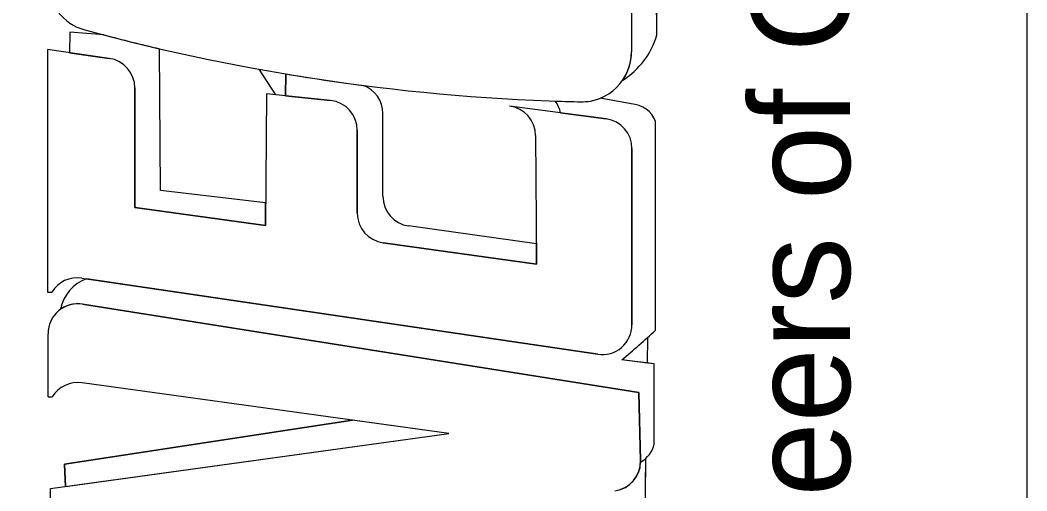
# Model space of a CAD drawing. Extents: x 1485751 to 1485785, y 230696.6 to 230718.6.
# Drawn here: x 1485783.769 to 1485784.533, y 230715.175 to 230715.532 of the extents above; entities that cross this region are included whole.
import ezdxf

# ---------------------------------------------------------------- set-up
doc = ezdxf.new("R2010")
doc.units = 0
doc.layers.add('SH_Border', color=7, linetype='Continuous')

msp = doc.modelspace()

# ---------------------------------------------------------------- linework, layer by layer
at = {"layer": 'SH_Border'}
for p, q in [((1485784.25235, 230715.52061), (1485784.25132, 230715.64075)), ((1485784.25235, 230715.52061), (1485784.25132, 230715.64075)), ((1485784.25235, 230715.52061), (1485784.25132, 230715.64075)), ((1485784.23301, 230715.61233), (1485784.23301, 230715.5077)), ((1485784.23301, 230715.61233), (1485784.23301, 230715.5077)), ((1485784.23301, 230715.61233), (1485784.23301, 230715.5077)), ((1485783.80699, 230715.52266), (1485783.80683, 230715.50714)), ((1485783.80699, 230715.52266), (1485783.80683, 230715.50714)), ((1485783.80699, 230715.52266), (1485783.80683, 230715.50714)), ((1485783.83291, 230715.52058), (1485783.80699, 230715.52266)), ((1485783.83291, 230715.52058), (1485783.80699, 230715.52266)), ((1485783.83291, 230715.52058), (1485783.80699, 230715.52266)), ((1485783.83689, 230715.50284), (1485783.79009, 230715.50953)), ((1485783.79009, 230715.50953), (1485783.79009, 230715.32551)), ((1485783.83689, 230715.50284), (1485783.79009, 230715.50953)), ((1485783.79009, 230715.50953), (1485783.79009, 230715.32551)), ((1485783.83689, 230715.50284), (1485783.79009, 230715.50953)), ((1485783.79009, 230715.50953), (1485783.79009, 230715.32551)), ((1485783.87574, 230715.40252), (1485783.87515, 230715.51016)), ((1485783.87574, 230715.40252), (1485783.87515, 230715.51016)), ((1485783.87574, 230715.40252), (1485783.87515, 230715.51016)), ((1485783.96336, 230715.47519), (1485783.95069, 230715.49456)), ((1485783.96336, 230715.47519), (1485783.95069, 230715.49456)), ((1485783.96336, 230715.47519), (1485783.95069, 230715.49456)), ((1485783.97073, 230715.47442), (1485783.97099, 230715.49103)), ((1485783.97073, 230715.47442), (1485783.97099, 230715.49103)), ((1485783.97073, 230715.47442), (1485783.97099, 230715.49103)), ((1485783.85637, 230715.38981), (1485783.85637, 230715.48038)), ((1485783.85637, 230715.38981), (1485783.85637, 230715.48038)), ((1485783.85637, 230715.38981), (1485783.85637, 230715.48038)), ((1485783.95622, 230715.47594), (1485783.95536, 230715.37602)), ((1485783.95622, 230715.47594), (1485783.95536, 230715.37602)), ((1485783.95622, 230715.47594), (1485783.95536, 230715.37602)), ((1485784.00475, 230715.47087), (1485783.95622, 230715.47594)), ((1485784.00475, 230715.47087), (1485783.95622, 230715.47594)), ((1485784.00475, 230715.47087), (1485783.95622, 230715.47594)), ((1485784.23285, 230715.46824), (1485784.20934, 230715.47262)), ((1485784.23285, 230715.46824), (1485784.20934, 230715.47262)), ((1485784.23285, 230715.46824), (1485784.20934, 230715.47262)), ((1485784.04446, 230715.39822), (1485784.04446, 230715.46102)), ((1485784.04446, 230715.39822), (1485784.04446, 230715.46102)), ((1485784.04446, 230715.39822), (1485784.04446, 230715.46102)), ((1485784.2137, 230715.45692), (1485784.14059, 230715.46667)), ((1485784.2137, 230715.45692), (1485784.14059, 230715.46667)), ((1485784.2137, 230715.45692), (1485784.14059, 230715.46667)), ((1485784.25132, 230715.29676), (1485784.25132, 230715.45489)), ((1485784.25132, 230715.29676), (1485784.25132, 230715.45489)), ((1485784.25132, 230715.29676), (1485784.25132, 230715.45489)), ((1485784.02508, 230715.38551), (1485784.02508, 230715.4483)), ((1485784.02508, 230715.38551), (1485784.02508, 230715.4483)), ((1485784.02508, 230715.38551), (1485784.02508, 230715.4483)), ((1485784.16028, 230715.44437), (1485784.16109, 230715.34674)), ((1485784.16028, 230715.44437), (1485784.16109, 230715.34674)), ((1485784.16028, 230715.44437), (1485784.16109, 230715.34674)), ((1485784.23339, 230715.30084), (1485784.23339, 230715.43443)), ((1485784.23339, 230715.30084), (1485784.23339, 230715.43443)), ((1485784.23339, 230715.30084), (1485784.23339, 230715.43443)), ((1485783.95551, 230715.39327), (1485783.87574, 230715.40252)), ((1485783.95551, 230715.39327), (1485783.87574, 230715.40252)), ((1485783.95551, 230715.39327), (1485783.87574, 230715.40252)), ((1485783.95536, 230715.37602), (1485783.85637, 230715.38981)), ((1485783.95536, 230715.37602), (1485783.85637, 230715.38981)), ((1485783.95536, 230715.37602), (1485783.85637, 230715.38981)), ((1485784.16096, 230715.36218), (1485784.064, 230715.37575)), ((1485784.16096, 230715.36218), (1485784.064, 230715.37575)), ((1485784.16096, 230715.36218), (1485784.064, 230715.37575)), ((1485784.16109, 230715.34674), (1485784.04463, 230715.36304)), ((1485784.16109, 230715.34674), (1485784.04463, 230715.36304)), ((1485784.16109, 230715.34674), (1485784.04463, 230715.36304)), ((1485783.81609, 230715.33622), (1485784.20739, 230715.2784)), ((1485783.81609, 230715.33622), (1485784.20739, 230715.2784)), ((1485783.81609, 230715.33622), (1485784.20739, 230715.2784)), ((1485783.79009, 230715.32551), (1485783.79336, 230715.32551)), ((1485783.79009, 230715.32551), (1485783.79336, 230715.32551)), ((1485783.79009, 230715.32551), (1485783.79336, 230715.32551)), ((1485784.23859, 230715.24939), (1485783.81676, 230715.31644)), ((1485784.23859, 230715.24939), (1485783.81676, 230715.31644)), ((1485784.23859, 230715.24939), (1485783.81676, 230715.31644)), ((1485783.79051, 230715.2461), (1485783.79051, 230715.29404)), ((1485783.79051, 230715.2461), (1485783.79051, 230715.29404)), ((1485783.79051, 230715.2461), (1485783.79051, 230715.29404)), ((1485784.2451, 230715.27174), (1485784.24545, 230715.29141)), ((1485784.2451, 230715.27174), (1485784.24545, 230715.29141)), ((1485784.2451, 230715.27174), (1485784.24545, 230715.29141)), ((1485784.2503, 230715.27109), (1485784.22567, 230715.27417)), ((1485784.2503, 230715.27109), (1485784.22567, 230715.27417)), ((1485784.2503, 230715.27109), (1485784.22567, 230715.27417)), ((1485784.2503, 230715.2105), (1485784.2503, 230715.27109)), ((1485784.2503, 230715.2105), (1485784.2503, 230715.27109)), ((1485784.2503, 230715.2105), (1485784.2503, 230715.27109)), ((1485784.09452, 230715.21839), (1485783.8163, 230715.25684)), ((1485784.09452, 230715.21839), (1485783.8163, 230715.25684)), ((1485784.09452, 230715.21839), (1485783.8163, 230715.25684)), ((1485784.23995, 230715.19789), (1485784.23859, 230715.24939)), ((1485784.23995, 230715.19789), (1485784.23859, 230715.24939)), ((1485784.23995, 230715.19789), (1485784.23859, 230715.24939)), ((1485783.79051, 230715.2461), (1485783.79378, 230715.2461)), ((1485783.79051, 230715.2461), (1485783.79378, 230715.2461)), ((1485783.79051, 230715.2461), (1485783.79378, 230715.2461)), ((1485783.80289, 230715.1951), (1485784.02153, 230715.22848)), ((1485783.80289, 230715.1951), (1485784.02153, 230715.22848)), ((1485783.80289, 230715.1951), (1485784.02153, 230715.22848)), ((1485783.79244, 230715.17654), (1485784.09452, 230715.21839)), ((1485783.79244, 230715.17654), (1485784.09452, 230715.21839)), ((1485783.79244, 230715.17654), (1485784.09452, 230715.21839)), ((1485783.80385, 230715.17812), (1485783.80289, 230715.1951)), ((1485783.80385, 230715.17812), (1485783.80289, 230715.1951)), ((1485783.80385, 230715.17812), (1485783.80289, 230715.1951)), ((1485784.24304, 230715.11402), (1485784.24376, 230715.19938)), ((1485784.24304, 230715.11402), (1485784.24376, 230715.19938)), ((1485784.24304, 230715.11402), (1485784.24376, 230715.19938)), ((1485783.79244, 230715.11608), (1485783.79244, 230715.17654)), ((1485783.79244, 230715.11608), (1485783.79244, 230715.17654)), ((1485783.79244, 230715.11608), (1485783.79244, 230715.17654))]:
    msp.add_line(p, q, dxfattribs=at)
msp.add_lwpolyline([(1485753.03285, 230718.14083), (1485784.53285, 230718.14083), (1485784.53285, 230697.14083), (1485753.03285, 230697.14083)], close=True, dxfattribs=at)
for points in [[(1485784.25235, 230715.52061), (1485784.25132, 230715.64075)], [(1485784.25235, 230715.52061), (1485784.25132, 230715.64075)], [(1485784.25235, 230715.52061), (1485784.25132, 230715.64075)], [(1485784.23301, 230715.61233), (1485784.23301, 230715.5077)], [(1485784.23301, 230715.61233), (1485784.23301, 230715.5077)], [(1485784.23301, 230715.61233), (1485784.23301, 230715.5077)], [(1485783.83291, 230715.52058), (1485783.80699, 230715.52266), (1485783.80683, 230715.50714), (1485783.83689, 230715.50284)], [(1485783.83291, 230715.52058), (1485783.80699, 230715.52266), (1485783.80683, 230715.50714), (1485783.83689, 230715.50284)], [(1485783.83291, 230715.52058), (1485783.80699, 230715.52266), (1485783.80683, 230715.50714), (1485783.83689, 230715.50284)], [(1485783.85637, 230715.48038), (1485783.85637, 230715.38981), (1485783.95536, 230715.37602), (1485783.95551, 230715.39327), (1485783.87574, 230715.40252), (1485783.87515, 230715.51016)], [(1485783.85637, 230715.48038), (1485783.85637, 230715.38981), (1485783.95536, 230715.37602), (1485783.95551, 230715.39327), (1485783.87574, 230715.40252), (1485783.87515, 230715.51016)], [(1485783.85637, 230715.48038), (1485783.85637, 230715.38981), (1485783.95536, 230715.37602), (1485783.95551, 230715.39327), (1485783.87574, 230715.40252), (1485783.87515, 230715.51016)], [(1485783.97099, 230715.49103), (1485783.97073, 230715.47442), (1485784.00475, 230715.47087)], [(1485783.97099, 230715.49103), (1485783.97073, 230715.47442), (1485784.00475, 230715.47087)], [(1485783.97099, 230715.49103), (1485783.97073, 230715.47442), (1485784.00475, 230715.47087)], [(1485784.23285, 230715.46824), (1485784.20934, 230715.47262)], [(1485784.23285, 230715.46824), (1485784.20934, 230715.47262)], [(1485784.23285, 230715.46824), (1485784.20934, 230715.47262)], [(1485784.04446, 230715.39822), (1485784.04446, 230715.46102)], [(1485784.04446, 230715.39822), (1485784.04446, 230715.46102)], [(1485784.04446, 230715.39822), (1485784.04446, 230715.46102)], [(1485784.17918, 230715.46152), (1485784.2137, 230715.45692)], [(1485784.17918, 230715.46152), (1485784.2137, 230715.45692)], [(1485784.17918, 230715.46152), (1485784.2137, 230715.45692)], [(1485784.25132, 230715.29676), (1485784.25132, 230715.45489)], [(1485784.25132, 230715.29676), (1485784.25132, 230715.45489)], [(1485784.25132, 230715.29676), (1485784.25132, 230715.45489)], [(1485784.02508, 230715.4483), (1485784.02508, 230715.38551)], [(1485784.02508, 230715.4483), (1485784.02508, 230715.38551)], [(1485784.02508, 230715.4483), (1485784.02508, 230715.38551)], [(1485784.23339, 230715.43443), (1485784.23339, 230715.30084)], [(1485784.23339, 230715.43443), (1485784.23339, 230715.30084)], [(1485784.23339, 230715.43443), (1485784.23339, 230715.30084)], [(1485784.04463, 230715.36304), (1485784.16109, 230715.34674), (1485784.16096, 230715.36218), (1485784.064, 230715.37575)], [(1485784.04463, 230715.36304), (1485784.16109, 230715.34674), (1485784.16096, 230715.36218), (1485784.064, 230715.37575)], [(1485784.04463, 230715.36304), (1485784.16109, 230715.34674), (1485784.16096, 230715.36218), (1485784.064, 230715.37575)], [(1485784.20739, 230715.2784), (1485783.81978, 230715.33567)], [(1485784.20739, 230715.2784), (1485783.81978, 230715.33567)], [(1485784.20739, 230715.2784), (1485783.81978, 230715.33567)], [(1485783.81676, 230715.31644), (1485784.23859, 230715.24939), (1485784.23995, 230715.19789)], [(1485783.81676, 230715.31644), (1485784.23859, 230715.24939), (1485784.23995, 230715.19789)], [(1485783.81676, 230715.31644), (1485784.23859, 230715.24939), (1485784.23995, 230715.19789)], [(1485784.2503, 230715.2105), (1485784.2503, 230715.27109), (1485784.2451, 230715.27174), (1485784.22567, 230715.27417)], [(1485784.2503, 230715.2105), (1485784.2503, 230715.27109), (1485784.2451, 230715.27174), (1485784.22567, 230715.27417)], [(1485784.2503, 230715.2105), (1485784.2503, 230715.27109), (1485784.2451, 230715.27174), (1485784.22567, 230715.27417)], [(1485783.80385, 230715.17812), (1485784.09452, 230715.21839), (1485784.02153, 230715.22848), (1485783.80289, 230715.1951), (1485783.80385, 230715.17812)], [(1485783.80385, 230715.17812), (1485784.09452, 230715.21839), (1485784.02153, 230715.22848), (1485783.80289, 230715.1951), (1485783.80385, 230715.17812)], [(1485783.80385, 230715.17812), (1485784.09452, 230715.21839), (1485784.02153, 230715.22848), (1485783.80289, 230715.1951), (1485783.80385, 230715.17812)], [(1485784.15842, 230715.16607), (1485784.18677, 230715.12362), (1485784.24304, 230715.11402), (1485784.24376, 230715.19938)], [(1485784.15842, 230715.16607), (1485784.18677, 230715.12362), (1485784.24304, 230715.11402), (1485784.24376, 230715.19938)], [(1485784.15842, 230715.16607), (1485784.18677, 230715.12362), (1485784.24304, 230715.11402), (1485784.24376, 230715.19938)]]:
    msp.add_lwpolyline(points, dxfattribs=at)
for centre, radius, start, end in [((1485783.82829, 230715.56095), 0.03781, 180, 254.79162), ((1485783.82829, 230715.56095), 0.03781, 180, 254.79162), ((1485783.82829, 230715.56095), 0.03781, 180, 254.79162), ((1485784.23016, 230717.0392), 1.56971, 254.79162, 268.69253), ((1485784.23016, 230717.0392), 1.56971, 254.79162, 268.69253), ((1485784.23016, 230717.0392), 1.56971, 254.79162, 268.69253), ((1485784.23016, 230717.0392), 1.56971, 255.34062, 256.92894), ((1485784.23016, 230717.0392), 1.56971, 255.34062, 256.92894), ((1485784.23016, 230717.0392), 1.56971, 255.34062, 256.92894), ((1485784.19322, 230715.53826), 0.06171, 302.39655, 343.37547), ((1485784.19322, 230715.53826), 0.06171, 302.39655, 343.37547), ((1485784.19322, 230715.53826), 0.06171, 302.39655, 343.37547), ((1485784.19322, 230715.53826), 0.06171, 302.39655, 343.37547), ((1485784.19322, 230715.53826), 0.06171, 302.39655, 343.37547), ((1485784.19322, 230715.53826), 0.06171, 302.39655, 343.37547), ((1485784.1952, 230715.5077), 0.03781, 268.69253, 0), ((1485784.1952, 230715.5077), 0.03781, 268.69253, 0), ((1485784.1952, 230715.5077), 0.03781, 268.69253, 0), ((1485784.1952, 230715.5077), 0.03781, 325.27661, 0), ((1485784.1952, 230715.5077), 0.03781, 325.27661, 0), ((1485784.1952, 230715.5077), 0.03781, 325.27661, 0), ((1485783.83368, 230715.48038), 0.02269, 0, 81.86464), ((1485783.83368, 230715.48038), 0.02269, 0, 81.86464), ((1485783.83368, 230715.48038), 0.02269, 0, 81.86464), ((1485783.83368, 230715.48038), 0.02269, 0, 81.86464), ((1485783.83368, 230715.48038), 0.02269, 0, 81.86464), ((1485783.83368, 230715.48038), 0.02269, 0, 81.86464), ((1485784.23016, 230717.0392), 1.56971, 260.49664, 262.65334), ((1485784.23016, 230717.0392), 1.56971, 260.49664, 262.65334), ((1485784.23016, 230717.0392), 1.56971, 260.49664, 262.65334), ((1485784.02177, 230715.46102), 0.02269, 0, 70.25544), ((1485784.02177, 230715.46102), 0.02269, 0, 70.25544), ((1485784.02177, 230715.46102), 0.02269, 0, 70.25544), ((1485784.02177, 230715.46102), 0.02269, 0, 70.25544), ((1485784.02177, 230715.46102), 0.02269, 0, 70.25544), ((1485784.02177, 230715.46102), 0.02269, 0, 70.25544), ((1485784.00239, 230715.4483), 0.02269, 0, 84.03166), ((1485784.00239, 230715.4483), 0.02269, 0, 84.03166), ((1485784.00239, 230715.4483), 0.02269, 0, 84.03166), ((1485784.00239, 230715.4483), 0.02269, 0, 84.03166), ((1485784.00239, 230715.4483), 0.02269, 0, 84.03166), ((1485784.00239, 230715.4483), 0.02269, 0, 84.03166), ((1485784.15697, 230715.4569), 0.02269, 11.76029, 36.6658), ((1485784.23016, 230717.0392), 1.56971, 267.99237, 268.69253), ((1485784.15697, 230715.4569), 0.02269, 11.76029, 36.6658), ((1485784.15697, 230715.4569), 0.02269, 11.76029, 36.6658), ((1485784.23016, 230717.0392), 1.56971, 267.99237, 268.69253), ((1485784.15697, 230715.4569), 0.02269, 11.76029, 36.6658), ((1485784.15697, 230715.4569), 0.02269, 11.76029, 36.6658), ((1485784.23016, 230717.0392), 1.56971, 267.99237, 268.69253), ((1485784.15697, 230715.4569), 0.02269, 11.76029, 36.6658), ((1485784.1952, 230715.5077), 0.03781, 268.69253, 291.95024), ((1485784.1952, 230715.5077), 0.03781, 268.69253, 291.95024), ((1485784.1952, 230715.5077), 0.03781, 268.69253, 291.95024), ((1485784.23207, 230715.44771), 0.02055, 20.45964, 87.82957), ((1485784.23207, 230715.44771), 0.02055, 20.45964, 87.82957), ((1485784.23207, 230715.44771), 0.02055, 20.45964, 87.82957), ((1485784.23207, 230715.44771), 0.02055, 20.45964, 87.82957), ((1485784.23207, 230715.44771), 0.02055, 20.45964, 87.82957), ((1485784.23207, 230715.44771), 0.02055, 20.45964, 87.82957), ((1485784.13759, 230715.44418), 0.02269, 0.4732, 82.40046), ((1485784.13759, 230715.44418), 0.02269, 0.4732, 82.40046), ((1485784.13759, 230715.44418), 0.02269, 0.4732, 82.40046), ((1485784.2107, 230715.43443), 0.02269, 0, 82.40046), ((1485784.2107, 230715.43443), 0.02269, 0, 82.40046), ((1485784.2107, 230715.43443), 0.02269, 0, 82.40046), ((1485784.2107, 230715.43443), 0.02269, 0, 82.40046), ((1485784.2107, 230715.43443), 0.02269, 0, 82.40046), ((1485784.2107, 230715.43443), 0.02269, 0, 82.40046), ((1485784.06714, 230715.39822), 0.02269, 180, 262.03311), ((1485784.06714, 230715.39822), 0.02269, 180, 262.03311), ((1485784.06714, 230715.39822), 0.02269, 180, 262.03311), ((1485784.06714, 230715.39822), 0.02269, 180, 262.03311), ((1485784.06714, 230715.39822), 0.02269, 180, 262.03311), ((1485784.06714, 230715.39822), 0.02269, 180, 262.03311), ((1485784.04777, 230715.38551), 0.02269, 180, 262.03311), ((1485784.04777, 230715.38551), 0.02269, 180, 262.03311), ((1485784.04777, 230715.38551), 0.02269, 180, 262.03311), ((1485784.04777, 230715.38551), 0.02269, 180, 262.03311), ((1485784.04777, 230715.38551), 0.02269, 180, 262.03311), ((1485784.04777, 230715.38551), 0.02269, 180, 262.03311), ((1485783.81278, 230715.31378), 0.02269, 81.59392, 148.85913), ((1485783.81278, 230715.31378), 0.02269, 81.59392, 148.85913), ((1485783.81278, 230715.31378), 0.02269, 81.59392, 148.85913), ((1485783.82978, 230715.30715), 0.03022, 109.32309, 169.78308), ((1485783.82978, 230715.30715), 0.03022, 109.32309, 169.78308), ((1485783.82978, 230715.30715), 0.03022, 109.32309, 169.78308), ((1485783.82978, 230715.30715), 0.03022, 109.32309, 169.78308), ((1485783.82978, 230715.30715), 0.03022, 109.32309, 169.78308), ((1485783.82978, 230715.30715), 0.03022, 109.32309, 169.78308), ((1485783.8132, 230715.29404), 0.02269, 80.96848, 180), ((1485783.8132, 230715.29404), 0.02269, 80.96848, 180), ((1485783.8132, 230715.29404), 0.02269, 80.96848, 180), ((1485783.8132, 230715.29404), 0.02269, 80.96848, 125.47349), ((1485783.8132, 230715.29404), 0.02269, 80.96848, 125.47349), ((1485783.8132, 230715.29404), 0.02269, 80.96848, 125.47349), ((1485784.2107, 230715.30084), 0.02269, 261.59392, 0), ((1485784.2107, 230715.30084), 0.02269, 261.59392, 0), ((1485784.2107, 230715.30084), 0.02269, 261.59392, 0), ((1485784.2107, 230715.30084), 0.02269, 261.59392, 0), ((1485784.2107, 230715.30084), 0.02269, 261.59392, 0), ((1485784.2107, 230715.30084), 0.02269, 261.59392, 0), ((1485783.73286, 230715.85967), 0.7653, 310.08662, 312.64602), ((1485783.73286, 230715.85967), 0.7653, 310.08662, 312.64602), ((1485783.73286, 230715.85967), 0.7653, 310.08662, 312.64602), ((1485783.73286, 230715.85967), 0.7653, 310.08662, 312.64602), ((1485783.73286, 230715.85967), 0.7653, 310.08662, 312.64602), ((1485783.73286, 230715.85967), 0.7653, 310.08662, 312.64602), ((1485783.8132, 230715.23437), 0.02269, 82.13091, 148.85913), ((1485783.8132, 230715.23437), 0.02269, 82.13091, 148.85913), ((1485783.8132, 230715.23437), 0.02269, 82.13091, 148.85913), ((1485784.2297, 230715.21513), 0.02111, 299.03105, 347.33987), ((1485784.2297, 230715.21513), 0.02111, 299.03105, 347.33987), ((1485784.2297, 230715.21513), 0.02111, 299.03105, 347.33987), ((1485784.2297, 230715.21513), 0.02111, 299.03105, 347.33987), ((1485784.2297, 230715.21513), 0.02111, 299.03105, 347.33987), ((1485784.2297, 230715.21513), 0.02111, 299.03105, 347.33987), ((1485784.21727, 230715.19729), 0.02269, 278.04089, 1.50643), ((1485784.21727, 230715.19729), 0.02269, 278.04089, 1.50643), ((1485784.21727, 230715.19729), 0.02269, 278.04089, 1.50643), ((1485784.21727, 230715.19729), 0.02269, 278.04089, 358.43264), ((1485784.21727, 230715.19729), 0.02269, 278.04089, 358.43264), ((1485784.21727, 230715.19729), 0.02269, 278.04089, 358.43264), ((1485784.21727, 230715.19729), 0.02269, 358.43264, 1.50643), ((1485784.21727, 230715.19729), 0.02269, 358.43264, 1.50643), ((1485784.21727, 230715.19729), 0.02269, 358.43264, 1.50643)]:
    msp.add_arc(centre, radius, start, end, dxfattribs=at)

# ---------------------------------------------------------------- texts
msp.add_text('Engineers of Ohio, Inc.', height=0.075625, rotation=90, dxfattribs=at).set_placement((1485784.39868, 230714.91187))

doc.saveas('drawing.dxf')
